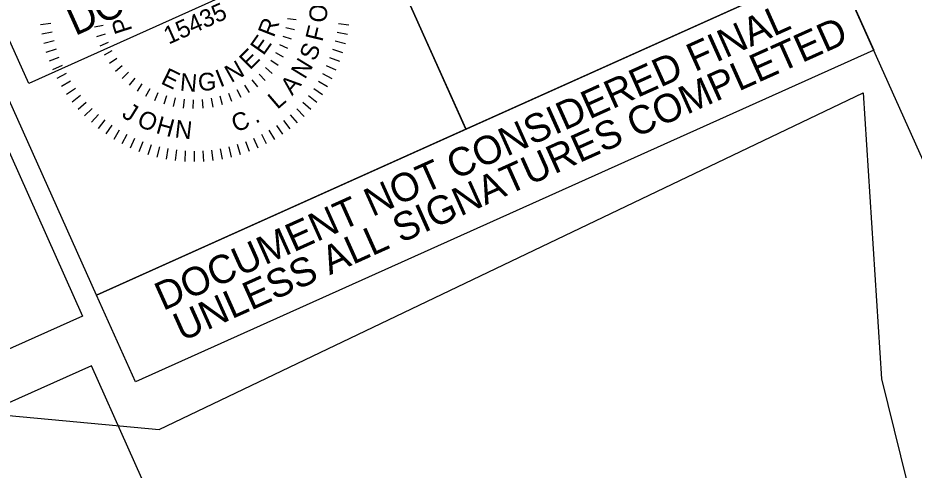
# Model space of a CAD drawing. Extents: x 553939 to 555925, y 502653 to 504347.
# Drawn here: x 555329.1 to 555550.6, y 504054.8 to 504166.5 of the extents above; entities that cross this region are included whole.
import ezdxf

# ---------------------------------------------------------------- set-up
doc = ezdxf.new("R2010")
doc.units = 0
for name, color, linetype in [('Old_Level_21', 7, 'Continuous'), ('Prop DSN Text', 7, 'Continuous'), ('Prop Horizontal Alignment Curve and Spiral Data', 7, 'Continuous'), ('Sheet Border Standard 30in CELL', 7, 'Continuous'), ('Sheet Clip Boundary CELL', 7, 'Continuous'), ('Sheet Sticker Exception Certification CELL', 7, 'Continuous'), ('Sheet Sticker Incomplete CELL', 7, 'Continuous')]:
    doc.layers.add(name, color=color, linetype=linetype)

msp = doc.modelspace()

# ---------------------------------------------------------------- linework, layer by layer
at = {"layer": 'Old_Level_21'}
for p, q in [((555334.71, 504164.84), (555337.32, 504165.15)), ((555348.06, 504164.27), (555350.19, 504164.71)), ((555397.91, 504165.97), (555395.75, 504166.26)), ((555410.94, 504164.66), (555408.35, 504164.99)), ((555335.06, 504162.54), (555337.63, 504163.01)), ((555348.67, 504161.91), (555350.75, 504162.55)), ((555397.47, 504163.56), (555395.34, 504164.06)), ((555410.59, 504162.37), (555408.02, 504162.85)), ((555335.54, 504160.27), (555338.08, 504160.9)), ((555349.5, 504159.61), (555351.51, 504160.45)), ((555396.79, 504161.22), (555394.73, 504161.92)), ((555410.1, 504160.11), (555407.56, 504160.74)), ((555336.16, 504158.04), (555338.66, 504158.81)), ((555350.55, 504157.4), (555352.47, 504158.43)), ((555395.89, 504158.94), (555393.9, 504159.84)), ((555409.47, 504157.87), (555406.97, 504158.66)), ((555336.91, 504155.85), (555339.36, 504156.77)), ((555351.81, 504155.31), (555353.62, 504156.52)), ((555393.46, 504154.71), (555391.68, 504155.97)), ((555394.78, 504156.77), (555392.89, 504157.85)), ((555408.71, 504155.68), (555406.26, 504156.62)), ((555337.8, 504153.7), (555340.18, 504154.77)), ((555353.27, 504153.34), (555354.95, 504154.72)), ((555391.94, 504152.79), (555390.3, 504154.22)), ((555407.82, 504153.55), (555405.43, 504154.62)), ((555338.81, 504151.61), (555341.13, 504152.82)), ((555354.91, 504151.53), (555356.45, 504153.06)), ((555356.72, 504149.88), (555358.1, 504151.56)), ((555390.25, 504151.02), (555388.75, 504152.6)), ((555406.79, 504151.46), (555404.48, 504152.68)), ((555339.94, 504149.59), (555342.18, 504150.94)), ((555341.19, 504147.64), (555343.35, 504149.12)), ((555358.67, 504148.42), (555359.89, 504150.22)), ((555386.4, 504148.02), (555385.23, 504149.86)), ((555388.4, 504149.43), (555387.06, 504151.15)), ((555405.65, 504149.44), (555403.42, 504150.8)), ((555342.56, 504145.77), (555344.63, 504147.38)), ((555360.76, 504147.14), (555361.8, 504149.06)), ((555362.96, 504146.08), (555363.82, 504148.09)), ((555365.26, 504145.24), (555365.91, 504147.32)), ((555379.73, 504145.03), (555379.13, 504147.13)), ((555382.05, 504145.81), (555381.25, 504147.84)), ((555384.28, 504146.81), (555383.29, 504148.75)), ((555403.01, 504145.63), (555400.95, 504147.25)), ((555404.39, 504147.5), (555402.24, 504148.99)), ((555344.05, 504143.98), (555346.01, 504145.71)), ((555367.62, 504144.62), (555368.07, 504146.75)), ((555370.04, 504144.23), (555370.28, 504146.4)), ((555372.48, 504144.08), (555372.51, 504146.26)), ((555374.92, 504144.16), (555374.74, 504146.34)), ((555376.94, 504146.62), (555377.33, 504144.47)), ((555401.52, 504143.86), (555399.57, 504145.6)), ((555345.63, 504142.29), (555347.49, 504144.14)), ((555347.32, 504140.7), (555349.06, 504142.65)), ((555398.24, 504140.58), (555396.5, 504142.55)), ((555399.93, 504142.17), (555398.08, 504144.02)), ((555349.09, 504139.21), (555350.71, 504141.27)), ((555396.45, 504139.1), (555394.84, 504141.17)), ((555350.96, 504137.83), (555352.45, 504139.98)), ((555352.91, 504136.57), (555354.26, 504138.8)), ((555392.63, 504136.48), (555391.28, 504138.72)), ((555394.58, 504137.73), (555393.1, 504139.89)), ((555354.92, 504135.43), (555356.14, 504137.74)), ((555357.01, 504134.4), (555358.08, 504136.79)), ((555359.15, 504133.51), (555360.08, 504135.96)), ((555386.37, 504133.45), (555385.45, 504135.9)), ((555388.52, 504134.33), (555387.45, 504136.72)), ((555390.61, 504135.35), (555389.4, 504137.67)), ((555361.34, 504132.75), (555362.12, 504135.25)), ((555363.57, 504132.12), (555364.2, 504134.66)), ((555365.83, 504131.63), (555366.31, 504134.2)), ((555368.13, 504131.28), (555368.45, 504133.87)), ((555370.44, 504131.06), (555370.6, 504133.67)), ((555372.76, 504130.99), (555372.76, 504133.6)), ((555375.07, 504131.05), (555374.92, 504133.67)), ((555377.38, 504131.25), (555377.07, 504133.86)), ((555379.68, 504131.6), (555379.21, 504134.17)), ((555381.95, 504132.08), (555381.32, 504134.62)), ((555384.18, 504132.7), (555383.41, 504135.2))]:
    msp.add_line(p, q, dxfattribs=at)
at = {"layer": 'Prop DSN Text'}
msp.add_lwpolyline([(555345.07, 504092.81), (555267.17, 504057.98), (555235.98, 504127.72), (555313.88, 504162.55)], close=True, dxfattribs=at)
at = {"layer": 'Prop Horizontal Alignment Curve and Spiral Data'}
msp.add_lwpolyline([(555073.67, 503958.23), (555091.71, 503918.08), (555365.32, 504040.41), (555347.29, 504080.56), (555073.67, 503958.23)], dxfattribs=at)
at = {"layer": 'Sheet Border Standard 30in CELL'}
msp.add_line((555393.76, 504241.63), (555439.82, 504139.05), dxfattribs=at)
for points in [[(555469.6, 504316.85), (554101.23, 503702.4), (554531.34, 502744.54), (555899.72, 503358.98)], [(555393.76, 504241.63), (555484.99, 504282.59), (555531.07, 504179.96), (555439.84, 504139)], [(555302.49, 504200.65), (555393.76, 504241.63), (555439.84, 504139), (555348.57, 504098.02)]]:
    msp.add_lwpolyline(points, close=True, dxfattribs=at)
at = {"layer": 'Sheet Clip Boundary CELL'}
for points in [[(554122.43, 503695.68), (555128.42, 504154.2), (555095.7, 504120), (555113.65, 504088.12), (555364.03, 504064.84), (555538.05, 504147.98), (555542.54, 504077.37), (555561.42, 504000.98), (555608.35, 503927.62), (555814.87, 503478.7), (555868.57, 503357.36), (555699.98, 503280.3), (555640.99, 503255.83), (555512.69, 503541.56), (555029.44, 503324.56), (555157.75, 503038.83), (555094.66, 503015.3), (554759.27, 502917.8)], [(554122.43, 503695.68), (555128.42, 504154.2), (555095.7, 504120), (555113.65, 504088.12), (555364.03, 504064.84), (555538.05, 504147.98), (555542.54, 504077.37), (555561.42, 504000.98), (555610.11, 503951.13), (555644.95, 503906.87), (555662.42, 503867.97), (555642.54, 503853.07), (555814.87, 503478.7), (555868.57, 503357.36), (555699.98, 503280.3), (555640.99, 503255.83), (555512.69, 503541.56), (555029.44, 503324.56), (555157.75, 503038.83), (555094.66, 503015.3), (554864.55, 502951)]]:
    msp.add_lwpolyline(points, dxfattribs=at)
at = {"layer": 'Sheet Sticker Exception Certification CELL'}
for p, q in [((555348.57, 504098.02), (555531.06, 504179.96)), ((555531.06, 504179.95), (555540.69, 504158.51)), ((555540.68, 504158.52), (555358.2, 504076.58)), ((555358.2, 504076.58), (555348.57, 504098.02))]:
    msp.add_line(p, q, dxfattribs=at)
at = {"layer": 'Sheet Sticker Incomplete CELL'}
msp.add_lwpolyline([(555331.81, 504150.28), (555319.77, 504177.08), (555487.4, 504252.35), (555499.43, 504225.55)], close=True, dxfattribs=at)

# ---------------------------------------------------------------- texts
at = {"layer": 'Old_Level_21'}
for s, height, rotation, p in [('15435', 4.358, 24.1017, (555366.4, 504159.86)), ('O ', 4.358, 85.1014, (555405.36, 504165.18)), ('P', 4.36, 108.2311, (555357.47, 504163.44)), ('R', 4.36, 68.6666, (555392.37, 504161.48)), ('F', 4.36, 76.3088, (555404.37, 504160.43)), ('E', 4.36, 54.8955, (555389.82, 504157.01)), ('S', 4.36, 67.4262, (555402.57, 504155.57)), ('E', 4.36, 44.9097, (555386.5, 504153.48)), ('N', 4.36, 29.5176, (555381.85, 504150.34)), ('N', 4.36, 58.5435, (555400.08, 504151.14)), ('E', 4.36, 334.1718, (555364.23, 504150.37)), ('I', 4.36, 21.8879, (555379.1, 504149.27)), ('N', 4.36, 355.0269, (555369.06, 504148.54)), ('G', 4.36, 3.7931, (555373.79, 504148.42)), ('A', 4.36, 49.7209, (555396.92, 504147.13)), ('L', 4.36, 40.7184, (555393.27, 504143.75)), ('J', 4.36, 328.0368, (555354.59, 504142.15)), ('O', 4.36, 336.1086, (555358.28, 504140)), ('C', 4.36, 20.1917, (555382.89, 504138.17)), ('H', 4.36, 344.7513, (555363.03, 504138.1)), ('N', 4.36, 353.4239, (555367.76, 504136.99)), ('.', 4.36, 27.934, (555387.88, 504140.28))]:
    msp.add_text(s, height=height, rotation=rotation, dxfattribs=at).set_placement(p)
at = {"layer": 'Sheet Sticker Exception Certification CELL'}
for s, p in [('DOCUMENT NOT CONSIDERED FINAL', (555365.03, 504094.07)), ('UNLESS ALL SIGNATURES COMPLETED', (555369.66, 504086.5))]:
    msp.add_text(s, height=7, rotation=24.1816, dxfattribs=at).set_placement(p)
at = {"layer": 'Sheet Sticker Incomplete CELL'}
msp.add_text('DO NOT USE FOR R/W ACQUISITION', height=7.2, rotation=24.1816, dxfattribs=at).set_placement((555343.29, 504161.97))

doc.saveas('drawing.dxf')
